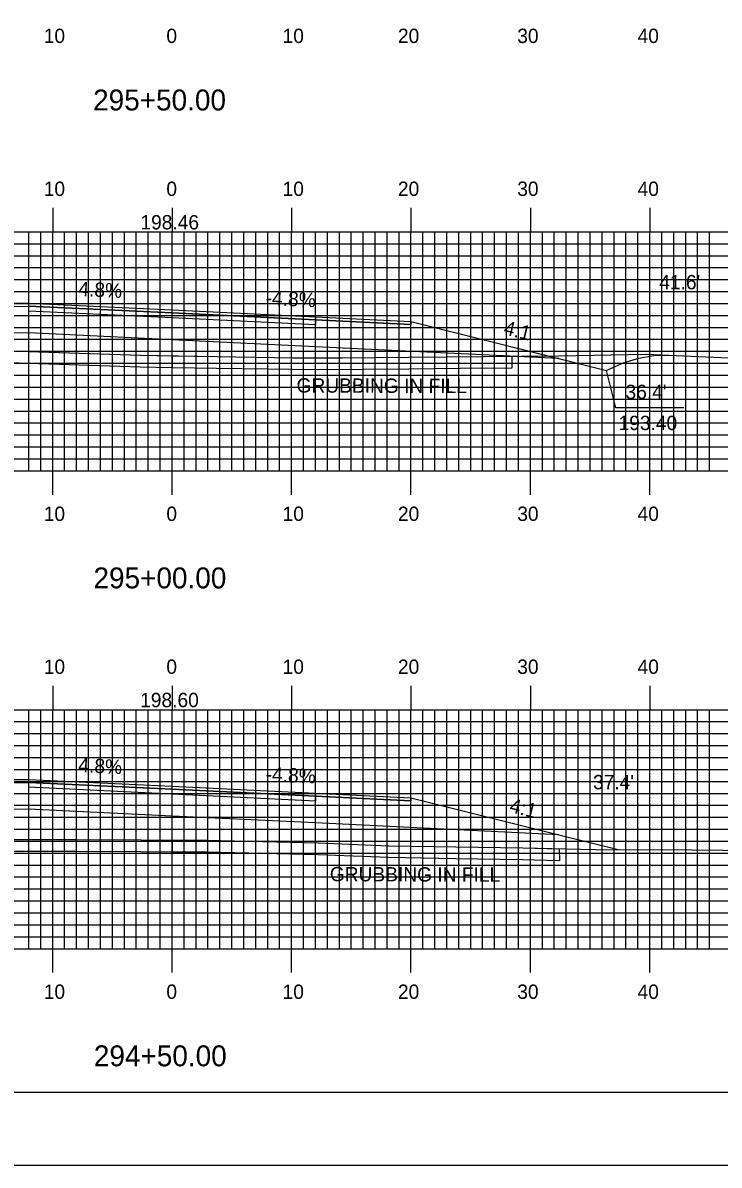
# Model space of a CAD drawing. Extents: x 1814522 to 1814865, y 442591 to 442811.
# Drawn here: x 1814675 to 1814733.3, y 442590.5 to 442686.2 of the extents above; entities that cross this region are included whole.
import ezdxf

# ---------------------------------------------------------------- set-up
doc = ezdxf.new("R2010")
doc.units = 0
for name, color, linetype in [('ANNOTATION', 7, 'Continuous'), ('BORDER', 7, 'Continuous'), ('D_Roadway_Centerline', 7, 'Continuous'), ('D_Roadway_Centerline_Text', 7, 'Continuous'), ('D_Roadway_Edge_Shoulder', 7, 'Continuous'), ('D_Roadway_Edge_TW', 7, 'Continuous'), ('D_Roadway_Pavement', 7, 'Continuous'), ('D_Roadway_SlopeLines', 7, 'Continuous'), ('D_Roadway_SubGrade', 7, 'Continuous'), ('D_Text_Standard', 7, 'Continuous'), ('GRUBBING IN FILL', 7, 'Continuous'), ('H_V ANNOTATION', 7, 'Continuous'), ('MAJOR', 7, 'Continuous'), ('MINOR', 7, 'Continuous'), ('PLOT BOUNDARY', 7, 'Continuous'), ('S_Roadway_Centerline', 7, 'Continuous')]:
    doc.layers.add(name, color=color, linetype=linetype)

msp = doc.modelspace()

# ---------------------------------------------------------------- linework, layer by layer
at = {"layer": 'ANNOTATION'}
msp.add_lwpolyline([(1814730.363, 442653.942), (1814724.672, 442653.942), (1814723.884, 442657.068)], dxfattribs=at)
at = {"layer": 'BORDER'}
msp.add_lwpolyline([(1814537.908, 442596.665), (1814857.908, 442596.665), (1814857.908, 442806.665), (1814537.908, 442806.665)], close=True, dxfattribs=at)
at = {"layer": 'D_Roadway_Centerline'}
for points in [[(1814651.128, 442658.443), (1814655.508, 442659.538), (1814656.638, 442659.82), (1814667.508, 442662.538), (1814675.508, 442662.698), (1814687.508, 442662.122), (1814699.508, 442661.546), (1814707.508, 442661.162), (1814719.884, 442658.068), (1814723.884, 442657.068), (1814724.096, 442657.174), (1814725.346, 442657.716), (1814726.596, 442658.092), (1814727.846, 442658.302), (1814729.096, 442658.346)], [(1814648.778, 442617.995), (1814655.508, 442619.677), (1814656.638, 442619.96), (1814667.508, 442622.677), (1814675.508, 442622.837), (1814687.508, 442622.261), (1814699.508, 442621.685), (1814707.508, 442621.301), (1814719.884, 442618.207), (1814724.865, 442616.962)]]:
    msp.add_lwpolyline(points, dxfattribs=at)
at = {"layer": 'D_Roadway_Edge_Shoulder'}
for points in [[(1814675.508, 442662.698), (1814667.508, 442662.538), (1814667.508, 442662.288), (1814675.508, 442662.448)], [(1814699.508, 442661.546), (1814707.508, 442661.162), (1814707.508, 442660.912), (1814699.508, 442661.296)], [(1814675.508, 442622.837), (1814667.508, 442622.677), (1814667.508, 442622.427), (1814675.508, 442622.587)], [(1814699.508, 442621.685), (1814707.508, 442621.301), (1814707.508, 442621.051), (1814699.508, 442621.435)]]:
    msp.add_lwpolyline(points, close=True, dxfattribs=at)
at = {"layer": 'D_Roadway_Edge_TW'}
for points in [[(1814675.508, 442662.448), (1814675.508, 442662.698), (1814687.508, 442662.122), (1814699.508, 442661.546), (1814699.508, 442661.296), (1814687.508, 442661.872)], [(1814675.508, 442622.587), (1814675.508, 442622.837), (1814687.508, 442622.261), (1814699.508, 442621.685), (1814699.508, 442621.435), (1814687.508, 442622.011)]]:
    msp.add_lwpolyline(points, close=True, dxfattribs=at)
at = {"layer": 'D_Roadway_Pavement'}
for points in [[(1814675.508, 442662.031), (1814675.508, 442662.448), (1814687.508, 442661.872), (1814699.508, 442661.296), (1814699.508, 442660.879), (1814687.508, 442661.455)], [(1814675.508, 442622.171), (1814675.508, 442622.587), (1814687.508, 442622.011), (1814699.508, 442621.435), (1814699.508, 442621.019), (1814687.508, 442621.595)]]:
    msp.add_lwpolyline(points, close=True, dxfattribs=at)
at = {"layer": 'D_Roadway_SlopeLines'}
for points in [[(1814707.508, 442661.162), (1814723.884, 442657.068)], [(1814723.884, 442657.068), (1814724.096, 442657.174), (1814725.346, 442657.716), (1814726.596, 442658.092), (1814727.846, 442658.302), (1814729.096, 442658.346)], [(1814707.508, 442621.301), (1814719.884, 442618.207), (1814724.865, 442616.962)]]:
    msp.add_lwpolyline(points, dxfattribs=at)
at = {"layer": 'D_Roadway_SubGrade'}
for points in [[(1814675.508, 442660.198), (1814656.638, 442659.82), (1814667.508, 442662.538), (1814667.508, 442662.288), (1814675.508, 442662.448), (1814687.508, 442661.872), (1814699.508, 442661.296), (1814707.508, 442660.912), (1814707.508, 442661.162), (1814719.884, 442658.068), (1814699.508, 442659.046), (1814687.508, 442659.622)], [(1814675.508, 442620.337), (1814656.638, 442619.96), (1814667.508, 442622.677), (1814667.508, 442622.427), (1814675.508, 442622.587), (1814687.508, 442622.011), (1814699.508, 442621.435), (1814707.508, 442621.051), (1814707.508, 442621.301), (1814719.884, 442618.207), (1814699.508, 442619.185), (1814687.508, 442619.761)]]:
    msp.add_lwpolyline(points, close=True, dxfattribs=at)
at = {"layer": 'GRUBBING IN FILL'}
for points in [[(1814656.638, 442658.518), (1814659.608, 442658.568), (1814667.028, 442658.692), (1814672.934, 442658.724), (1814678.897, 442658.53), (1814684.86, 442658.336), (1814687.508, 442658.289), (1814687.508, 442657.289), (1814684.835, 442657.336), (1814678.883, 442657.53), (1814672.93, 442657.724), (1814667.028, 442657.691), (1814661.833, 442657.605), (1814656.638, 442657.518)], [(1814656.638, 442658.518), (1814659.608, 442658.568), (1814667.028, 442658.692), (1814672.934, 442658.724), (1814678.897, 442658.53), (1814684.86, 442658.336), (1814687.508, 442658.289), (1814687.508, 442657.289), (1814684.835, 442657.336), (1814678.883, 442657.53), (1814672.93, 442657.724), (1814667.028, 442657.691), (1814661.833, 442657.605), (1814656.638, 442657.518)], [(1814687.508, 442658.289), (1814691.246, 442658.223), (1814697.632, 442658.11), (1814701.767, 442658.129), (1814707.313, 442658.166), (1814713.587, 442658.231), (1814715.955, 442658.256), (1814715.955, 442657.256), (1814711.638, 442657.211), (1814707.322, 442657.166), (1814699.699, 442657.119), (1814691.23, 442657.223), (1814687.508, 442657.289)], [(1814687.508, 442658.289), (1814691.246, 442658.223), (1814697.632, 442658.11), (1814701.767, 442658.129), (1814707.313, 442658.166), (1814713.587, 442658.231), (1814715.955, 442658.256), (1814715.955, 442657.256), (1814711.638, 442657.211), (1814707.322, 442657.166), (1814699.699, 442657.119), (1814691.23, 442657.223), (1814687.508, 442657.289)], [(1814656.638, 442617.761), (1814658.431, 442617.728), (1814666.601, 442617.728), (1814676.646, 442617.802), (1814684.916, 442617.767), (1814687.508, 442617.751), (1814687.508, 442616.751), (1814684.907, 442616.767), (1814679.401, 442616.8), (1814673.892, 442616.804), (1814666.585, 442616.728), (1814659.277, 442616.652), (1814656.638, 442616.879)], [(1814656.638, 442617.761), (1814658.431, 442617.728), (1814666.601, 442617.728), (1814676.646, 442617.802), (1814684.916, 442617.767), (1814687.508, 442617.751), (1814687.508, 442616.751), (1814684.907, 442616.767), (1814679.401, 442616.8), (1814673.892, 442616.804), (1814666.585, 442616.728), (1814659.277, 442616.652), (1814656.638, 442616.879)], [(1814687.508, 442617.751), (1814690.427, 442617.734), (1814695.085, 442617.628), (1814699.743, 442617.522), (1814705.658, 442617.284), (1814711.263, 442617.189), (1814716.869, 442617.095), (1814719.913, 442617.031), (1814719.939, 442616.03), (1814716.85, 442616.095), (1814711.24, 442616.19), (1814705.629, 442616.284), (1814699.711, 442616.522), (1814690.412, 442616.734), (1814687.508, 442616.751)], [(1814687.508, 442617.751), (1814690.427, 442617.734), (1814695.085, 442617.628), (1814699.743, 442617.522), (1814705.658, 442617.284), (1814711.263, 442617.189), (1814716.869, 442617.095), (1814719.913, 442617.031), (1814719.939, 442616.03), (1814716.85, 442616.095), (1814711.24, 442616.19), (1814705.629, 442616.284), (1814699.711, 442616.522), (1814690.412, 442616.734), (1814687.508, 442616.751)]]:
    msp.add_lwpolyline(points, close=True, dxfattribs=at)
at = {"layer": 'MAJOR'}
for p, q in [((1814677.508, 442670.669), (1814677.508, 442668.665)), ((1814687.508, 442670.669), (1814687.508, 442668.665)), ((1814697.508, 442670.669), (1814697.508, 442668.665)), ((1814707.508, 442670.669), (1814707.508, 442668.665)), ((1814717.508, 442670.669), (1814717.508, 442668.665)), ((1814727.508, 442670.669), (1814727.508, 442668.665)), ((1814547.508, 442668.665), (1814827.508, 442668.665)), ((1814547.508, 442668.665), (1814827.508, 442668.665)), ((1814677.508, 442648.665), (1814677.508, 442668.665)), ((1814687.508, 442648.665), (1814687.508, 442668.665)), ((1814697.508, 442648.665), (1814697.508, 442668.665)), ((1814707.508, 442648.665), (1814707.508, 442668.665)), ((1814717.508, 442648.665), (1814717.508, 442668.665)), ((1814727.508, 442648.665), (1814727.508, 442668.665)), ((1814547.508, 442663.665), (1814827.508, 442663.665)), ((1814547.508, 442658.665), (1814827.508, 442658.665)), ((1814547.508, 442653.665), (1814827.508, 442653.665)), ((1814547.508, 442648.665), (1814827.508, 442648.665)), ((1814547.508, 442648.665), (1814827.508, 442648.665)), ((1814677.508, 442646.661), (1814677.508, 442648.665)), ((1814687.508, 442646.661), (1814687.508, 442648.665)), ((1814697.508, 442646.661), (1814697.508, 442648.665)), ((1814707.508, 442646.661), (1814707.508, 442648.665)), ((1814717.508, 442646.661), (1814717.508, 442648.665)), ((1814727.508, 442646.661), (1814727.508, 442648.665)), ((1814677.508, 442630.669), (1814677.508, 442628.665)), ((1814687.508, 442630.669), (1814687.508, 442628.665)), ((1814697.508, 442630.669), (1814697.508, 442628.665)), ((1814707.508, 442630.669), (1814707.508, 442628.665)), ((1814717.508, 442630.669), (1814717.508, 442628.665)), ((1814727.508, 442630.669), (1814727.508, 442628.665)), ((1814547.508, 442628.665), (1814827.508, 442628.665)), ((1814547.508, 442628.665), (1814827.508, 442628.665)), ((1814677.508, 442608.665), (1814677.508, 442628.665)), ((1814687.508, 442608.665), (1814687.508, 442628.665)), ((1814697.508, 442608.665), (1814697.508, 442628.665)), ((1814707.508, 442608.665), (1814707.508, 442628.665)), ((1814717.508, 442608.665), (1814717.508, 442628.665)), ((1814727.508, 442608.665), (1814727.508, 442628.665)), ((1814547.508, 442623.665), (1814827.508, 442623.665)), ((1814547.508, 442618.665), (1814827.508, 442618.665)), ((1814547.508, 442613.665), (1814827.508, 442613.665)), ((1814547.508, 442608.665), (1814827.508, 442608.665)), ((1814547.508, 442608.665), (1814827.508, 442608.665)), ((1814677.508, 442606.661), (1814677.508, 442608.665)), ((1814687.508, 442606.661), (1814687.508, 442608.665)), ((1814697.508, 442606.661), (1814697.508, 442608.665)), ((1814707.508, 442606.661), (1814707.508, 442608.665)), ((1814717.508, 442606.661), (1814717.508, 442608.665)), ((1814727.508, 442606.661), (1814727.508, 442608.665))]:
    msp.add_line(p, q, dxfattribs=at)
at = {"layer": 'MINOR'}
for p, q in [((1814675.508, 442648.665), (1814675.508, 442668.665)), ((1814676.508, 442648.665), (1814676.508, 442668.665)), ((1814678.508, 442648.665), (1814678.508, 442668.665)), ((1814679.508, 442648.665), (1814679.508, 442668.665)), ((1814680.508, 442648.665), (1814680.508, 442668.665)), ((1814681.508, 442648.665), (1814681.508, 442668.665)), ((1814682.508, 442648.665), (1814682.508, 442668.665)), ((1814683.508, 442648.665), (1814683.508, 442668.665)), ((1814684.508, 442648.665), (1814684.508, 442668.665)), ((1814685.508, 442648.665), (1814685.508, 442668.665)), ((1814686.508, 442648.665), (1814686.508, 442668.665)), ((1814688.508, 442648.665), (1814688.508, 442668.665)), ((1814689.508, 442648.665), (1814689.508, 442668.665)), ((1814690.508, 442648.665), (1814690.508, 442668.665)), ((1814691.508, 442648.665), (1814691.508, 442668.665)), ((1814692.508, 442648.665), (1814692.508, 442668.665)), ((1814693.508, 442648.665), (1814693.508, 442668.665)), ((1814694.508, 442648.665), (1814694.508, 442668.665)), ((1814695.508, 442648.665), (1814695.508, 442668.665)), ((1814696.508, 442648.665), (1814696.508, 442668.665)), ((1814698.508, 442648.665), (1814698.508, 442668.665)), ((1814699.508, 442648.665), (1814699.508, 442668.665)), ((1814700.508, 442648.665), (1814700.508, 442668.665)), ((1814701.508, 442648.665), (1814701.508, 442668.665)), ((1814702.508, 442648.665), (1814702.508, 442668.665)), ((1814703.508, 442648.665), (1814703.508, 442668.665)), ((1814704.508, 442648.665), (1814704.508, 442668.665)), ((1814705.508, 442648.665), (1814705.508, 442668.665)), ((1814706.508, 442648.665), (1814706.508, 442668.665)), ((1814708.508, 442648.665), (1814708.508, 442668.665)), ((1814709.508, 442648.665), (1814709.508, 442668.665)), ((1814710.508, 442648.665), (1814710.508, 442668.665)), ((1814711.508, 442648.665), (1814711.508, 442668.665)), ((1814712.508, 442648.665), (1814712.508, 442668.665)), ((1814713.508, 442648.665), (1814713.508, 442668.665)), ((1814714.508, 442648.665), (1814714.508, 442668.665)), ((1814715.508, 442648.665), (1814715.508, 442668.665)), ((1814716.508, 442648.665), (1814716.508, 442668.665)), ((1814718.508, 442648.665), (1814718.508, 442668.665)), ((1814719.508, 442648.665), (1814719.508, 442668.665)), ((1814720.508, 442648.665), (1814720.508, 442668.665)), ((1814721.508, 442648.665), (1814721.508, 442668.665)), ((1814722.508, 442648.665), (1814722.508, 442668.665)), ((1814723.508, 442648.665), (1814723.508, 442668.665)), ((1814724.508, 442648.665), (1814724.508, 442668.665)), ((1814725.508, 442648.665), (1814725.508, 442668.665)), ((1814726.508, 442648.665), (1814726.508, 442668.665)), ((1814728.508, 442648.665), (1814728.508, 442668.665)), ((1814729.508, 442648.665), (1814729.508, 442668.665)), ((1814730.508, 442648.665), (1814730.508, 442668.665)), ((1814731.508, 442648.665), (1814731.508, 442668.665)), ((1814732.508, 442648.665), (1814732.508, 442668.665)), ((1814547.508, 442667.665), (1814827.508, 442667.665)), ((1814547.508, 442666.665), (1814827.508, 442666.665)), ((1814547.508, 442665.665), (1814827.508, 442665.665)), ((1814547.508, 442664.665), (1814827.508, 442664.665)), ((1814547.508, 442662.665), (1814827.508, 442662.665)), ((1814547.508, 442661.665), (1814827.508, 442661.665)), ((1814547.508, 442660.665), (1814827.508, 442660.665)), ((1814547.508, 442659.665), (1814827.508, 442659.665)), ((1814547.508, 442657.665), (1814827.508, 442657.665)), ((1814547.508, 442656.665), (1814827.508, 442656.665)), ((1814547.508, 442655.665), (1814827.508, 442655.665)), ((1814547.508, 442654.665), (1814827.508, 442654.665)), ((1814547.508, 442652.665), (1814827.508, 442652.665)), ((1814547.508, 442651.665), (1814827.508, 442651.665)), ((1814547.508, 442650.665), (1814827.508, 442650.665)), ((1814547.508, 442649.665), (1814827.508, 442649.665)), ((1814675.508, 442608.665), (1814675.508, 442628.665)), ((1814676.508, 442608.665), (1814676.508, 442628.665)), ((1814678.508, 442608.665), (1814678.508, 442628.665)), ((1814679.508, 442608.665), (1814679.508, 442628.665)), ((1814680.508, 442608.665), (1814680.508, 442628.665)), ((1814681.508, 442608.665), (1814681.508, 442628.665)), ((1814682.508, 442608.665), (1814682.508, 442628.665)), ((1814683.508, 442608.665), (1814683.508, 442628.665)), ((1814684.508, 442608.665), (1814684.508, 442628.665)), ((1814685.508, 442608.665), (1814685.508, 442628.665)), ((1814686.508, 442608.665), (1814686.508, 442628.665)), ((1814688.508, 442608.665), (1814688.508, 442628.665)), ((1814689.508, 442608.665), (1814689.508, 442628.665)), ((1814690.508, 442608.665), (1814690.508, 442628.665)), ((1814691.508, 442608.665), (1814691.508, 442628.665)), ((1814692.508, 442608.665), (1814692.508, 442628.665)), ((1814693.508, 442608.665), (1814693.508, 442628.665)), ((1814694.508, 442608.665), (1814694.508, 442628.665)), ((1814695.508, 442608.665), (1814695.508, 442628.665)), ((1814696.508, 442608.665), (1814696.508, 442628.665)), ((1814698.508, 442608.665), (1814698.508, 442628.665)), ((1814699.508, 442608.665), (1814699.508, 442628.665)), ((1814700.508, 442608.665), (1814700.508, 442628.665)), ((1814701.508, 442608.665), (1814701.508, 442628.665)), ((1814702.508, 442608.665), (1814702.508, 442628.665)), ((1814703.508, 442608.665), (1814703.508, 442628.665)), ((1814704.508, 442608.665), (1814704.508, 442628.665)), ((1814705.508, 442608.665), (1814705.508, 442628.665)), ((1814706.508, 442608.665), (1814706.508, 442628.665)), ((1814708.508, 442608.665), (1814708.508, 442628.665)), ((1814709.508, 442608.665), (1814709.508, 442628.665)), ((1814710.508, 442608.665), (1814710.508, 442628.665)), ((1814711.508, 442608.665), (1814711.508, 442628.665)), ((1814712.508, 442608.665), (1814712.508, 442628.665)), ((1814713.508, 442608.665), (1814713.508, 442628.665)), ((1814714.508, 442608.665), (1814714.508, 442628.665)), ((1814715.508, 442608.665), (1814715.508, 442628.665)), ((1814716.508, 442608.665), (1814716.508, 442628.665)), ((1814718.508, 442608.665), (1814718.508, 442628.665)), ((1814719.508, 442608.665), (1814719.508, 442628.665)), ((1814720.508, 442608.665), (1814720.508, 442628.665)), ((1814721.508, 442608.665), (1814721.508, 442628.665)), ((1814722.508, 442608.665), (1814722.508, 442628.665)), ((1814723.508, 442608.665), (1814723.508, 442628.665)), ((1814724.508, 442608.665), (1814724.508, 442628.665)), ((1814725.508, 442608.665), (1814725.508, 442628.665)), ((1814726.508, 442608.665), (1814726.508, 442628.665)), ((1814728.508, 442608.665), (1814728.508, 442628.665)), ((1814729.508, 442608.665), (1814729.508, 442628.665)), ((1814730.508, 442608.665), (1814730.508, 442628.665)), ((1814731.508, 442608.665), (1814731.508, 442628.665)), ((1814732.508, 442608.665), (1814732.508, 442628.665)), ((1814547.508, 442627.665), (1814827.508, 442627.665)), ((1814547.508, 442626.665), (1814827.508, 442626.665)), ((1814547.508, 442625.665), (1814827.508, 442625.665)), ((1814547.508, 442624.665), (1814827.508, 442624.665)), ((1814547.508, 442622.665), (1814827.508, 442622.665)), ((1814547.508, 442621.665), (1814827.508, 442621.665)), ((1814547.508, 442620.665), (1814827.508, 442620.665)), ((1814547.508, 442619.665), (1814827.508, 442619.665)), ((1814547.508, 442617.665), (1814827.508, 442617.665)), ((1814547.508, 442616.665), (1814827.508, 442616.665)), ((1814547.508, 442615.665), (1814827.508, 442615.665)), ((1814547.508, 442614.665), (1814827.508, 442614.665)), ((1814547.508, 442612.665), (1814827.508, 442612.665)), ((1814547.508, 442611.665), (1814827.508, 442611.665)), ((1814547.508, 442610.665), (1814827.508, 442610.665)), ((1814547.508, 442609.665), (1814827.508, 442609.665))]:
    msp.add_line(p, q, dxfattribs=at)
at = {"layer": 'PLOT BOUNDARY'}
msp.add_lwpolyline([(1814521.721, 442590.547), (1814861.721, 442590.547), (1814861.721, 442810.547), (1814521.721, 442810.547)], close=True, dxfattribs=at)
at = {"layer": 'S_Roadway_Centerline'}
for points in [[(1814547.508, 442659.883), (1814554.061, 442660.02), (1814565.763, 442659.35), (1814571.631, 442659.132), (1814576.17, 442658.826), (1814587.171, 442658.471), (1814590.92, 442658.569), (1814604.613, 442658.158), (1814607.228, 442658.032), (1814627.098, 442658.565), (1814636.481, 442658.76), (1814637.549, 442658.763), (1814651.161, 442658.442), (1814652.188, 442658.444), (1814667.028, 442658.692), (1814669.782, 442658.646), (1814672.934, 442658.724), (1814684.86, 442658.336), (1814697.632, 442658.11), (1814701.767, 442658.129), (1814707.313, 442658.166), (1814719.862, 442658.297), (1814727.24, 442658.436), (1814735.311, 442658.047)], [(1814623.209, 442618.44), (1814639.265, 442618.387), (1814640.725, 442618.321), (1814655.687, 442617.715), (1814657.548, 442617.804), (1814659.315, 442617.653), (1814673.887, 442617.804), (1814679.405, 442617.8), (1814690.427, 442617.734), (1814699.743, 442617.522), (1814705.658, 442617.284), (1814716.869, 442617.095), (1814722.958, 442616.967), (1814730.994, 442616.946), (1814738.896, 442616.855)]]:
    msp.add_lwpolyline(points, dxfattribs=at)

# ---------------------------------------------------------------- texts
at = {"layer": 'ANNOTATION'}
for s, rotation, p in [('4.8%', 357.25191, (1814679.637, 442663.302)), ('-4.8%', 357.25191, (1814695.316, 442662.549)), ('4:1', 345.96376, (1814715.202, 442660.1)), ('4.8%', 357.25191, (1814679.637, 442623.442)), ('-4.8%', 357.25191, (1814695.316, 442622.689)), ('4:1', 345.96376, (1814715.692, 442620.117))]:
    msp.add_text(s, height=1.2, rotation=rotation, dxfattribs=at).set_placement(p)
for s, p in [("36.4'", (1814725.471, 442654.668)), ('193.40', (1814724.888, 442652.068))]:
    msp.add_text(s, height=1.2, dxfattribs=at).set_placement(p)
at = {"layer": 'D_Roadway_Centerline'}
for s, p in [('C', (1814687.502, 442662.122)), ('L', (1814687.508, 442662.115)), ('C', (1814687.502, 442622.261)), ('L', (1814687.508, 442622.254))]:
    msp.add_text(s, height=0.0146, dxfattribs=at).set_placement(p)
at = {"layer": 'D_Roadway_Centerline_Text'}
for s, p in [('198.46', (1814684.854, 442668.864)), ('198.60', (1814684.832, 442628.877))]:
    msp.add_text(s, height=1.2, dxfattribs=at).set_placement(p)
at = {"layer": 'D_Text_Standard'}
for s, p in [("41.6'", (1814728.296, 442663.852)), ("37.4'", (1814722.752, 442622.006))]:
    msp.add_text(s, height=1.2, dxfattribs=at).set_placement(p)
at = {"layer": 'GRUBBING IN FILL'}
for p in [(1814697.923, 442655.21), (1814700.709, 442614.31)]:
    msp.add_text('GRUBBING IN FILL', height=1.2, rotation=359.80532, dxfattribs=at).set_placement(p)
at = {"layer": 'H_V ANNOTATION'}
for s, height, p in [('10', 1.2, (1814676.758, 442684.465)), ('0', 1.2, (1814687.026, 442684.465)), ('10', 1.2, (1814696.758, 442684.465)), ('20', 1.2, (1814706.415, 442684.465)), ('30', 1.2, (1814716.405, 442684.465)), ('40', 1.2, (1814726.48, 442684.465)), ('295+50.00', 1.75, (1814680.89, 442678.821)), ('10', 1.2, (1814676.758, 442671.665)), ('0', 1.2, (1814687.026, 442671.665)), ('10', 1.2, (1814696.758, 442671.665)), ('20', 1.2, (1814706.415, 442671.665)), ('30', 1.2, (1814716.405, 442671.665)), ('40', 1.2, (1814726.48, 442671.665)), ('10', 1.2, (1814676.758, 442644.465)), ('0', 1.2, (1814687.026, 442644.465)), ('10', 1.2, (1814696.758, 442644.465)), ('20', 1.2, (1814706.415, 442644.465)), ('30', 1.2, (1814716.405, 442644.465)), ('40', 1.2, (1814726.48, 442644.465)), ('295+00.00', 1.75, (1814680.922, 442638.821)), ('10', 1.2, (1814676.758, 442631.665)), ('0', 1.2, (1814687.026, 442631.665)), ('10', 1.2, (1814696.758, 442631.665)), ('20', 1.2, (1814706.415, 442631.665)), ('30', 1.2, (1814716.405, 442631.665)), ('40', 1.2, (1814726.48, 442631.665)), ('10', 1.2, (1814676.758, 442604.465)), ('0', 1.2, (1814687.026, 442604.465)), ('10', 1.2, (1814696.758, 442604.465)), ('20', 1.2, (1814706.415, 442604.465)), ('30', 1.2, (1814716.405, 442604.465)), ('40', 1.2, (1814726.48, 442604.465)), ('294+50.00', 1.75, (1814680.953, 442598.821))]:
    msp.add_text(s, height=height, dxfattribs=at).set_placement(p)

doc.saveas('drawing.dxf')
